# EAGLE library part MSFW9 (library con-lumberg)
MSF CONNECTOR
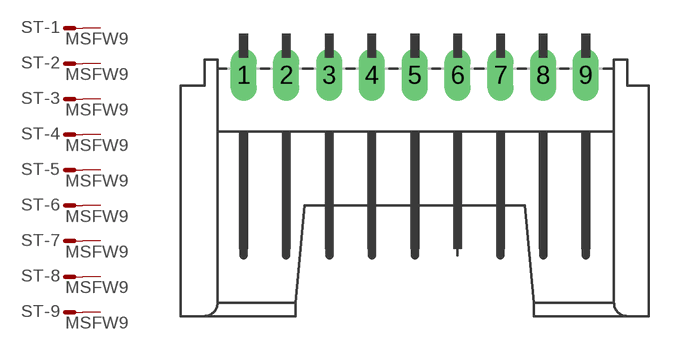
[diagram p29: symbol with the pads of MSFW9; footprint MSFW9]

Designator prefix ST; gates -1=M -2=M -3=M -4=M -5=M -6=M -7=M -8=M -9=M

## MSFW9 (OC_FARNELL: unknown; OC_NEWARK: unknown)  [MSFW9]
1  -1:S  pas
2  -2:S  pas
3  -3:S  pas
4  -4:S  pas
5  -5:S  pas
6  -6:S  pas
7  -7:S  pas
8  -8:S  pas
9  -9:S  pas

## Footprint MSFW9 (pad centres in mm)
MSF CONNECTOR
drill 1.016 long: 1 0,1.905; 2 2.489,1.905; 3 5.004,1.905; 4 7.493,1.905; 5 10.008,1.905; 6 12.497,1.905; 7 15.011,1.905; 8 17.501,1.905; 9 19.99,1.905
